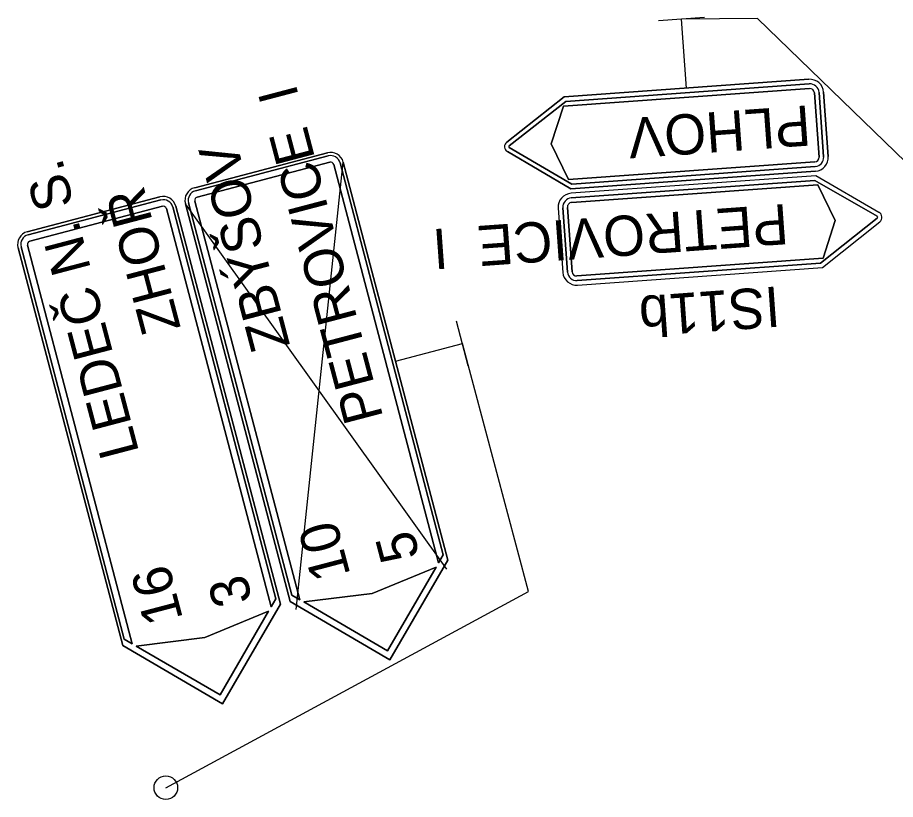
# Model space of a CAD drawing. Extents: x -688893 to -679983, y -1088371 to -1075771.
# Drawn here: x -687166 to -686022, y -1078650 to -1077631 of the extents above; entities that cross this region are included whole.
import ezdxf

# ---------------------------------------------------------------- set-up
doc = ezdxf.new("R2010")
doc.units = 0
for name, color, linetype in [('S SDZ', 7, 'Continuous'), ('S SDZ plochy', 7, 'Continuous'), ('S SDZ symbol', 7, 'Continuous'), ('SDZ', 7, 'Continuous'), ('SDZ ozn', 7, 'Continuous'), ('SDZ plochy', 7, 'Continuous'), ('SDZ symbol', 7, 'Continuous')]:
    doc.layers.add(name, color=color, linetype=linetype)

msp = doc.modelspace()

# ---------------------------------------------------------------- linework, layer by layer
at = {"layer": 'S SDZ'}
for p, q in [((-686762.4, -1077806.8), (-686935.3, -1077852.3)), ((-686761.3, -1077810.9), (-686934.2, -1077856.4)), ((-686932, -1077864.6), (-686759.2, -1077819.2)), ((-686617.5, -1078341.1), (-686754, -1077822.2)), ((-686611.4, -1078330.7), (-686745.8, -1077820)), ((-686605.2, -1078337.5), (-686741.6, -1077818.9)), ((-686980.6, -1077864.2), (-687153.4, -1077909.7)), ((-686979.5, -1077868.3), (-687152.3, -1077913.8)), ((-686943.3, -1077872), (-686808.8, -1078383.1)), ((-686935.1, -1077869.8), (-686798.4, -1078389.2)), ((-687150.2, -1077922), (-686977.3, -1077876.5)), ((-686835.6, -1078398.5), (-686972.1, -1077879.6)), ((-686829.5, -1078388.1), (-686963.9, -1077877.4)), ((-686823.3, -1078394.9), (-686959.8, -1077876.3)), ((-686947.4, -1077873.1), (-686811, -1078391.6)), ((-687161.4, -1077929.4), (-687027, -1078440.5)), ((-687153.2, -1077927.2), (-687016.6, -1078446.6)), ((-687165.5, -1077930.5), (-687029.1, -1078449)), ((-686681, -1078467.5), (-686605.2, -1078337.5)), ((-686617.5, -1078341.1), (-686611.4, -1078330.7)), ((-686620.8, -1078346.9), (-686703.8, -1078381)), ((-686684.1, -1078455.9), (-686620.8, -1078346.9)), ((-686808.8, -1078383.1), (-686798.4, -1078389.2)), ((-686703.8, -1078381), (-686793.2, -1078392.2)), ((-686899.2, -1078524.8), (-686823.3, -1078394.9)), ((-686835.6, -1078398.5), (-686829.5, -1078388.1)), ((-686811, -1078391.6), (-686681, -1078467.5)), ((-686793.2, -1078392.2), (-686684.1, -1078455.9)), ((-686838.9, -1078404.3), (-686921.9, -1078438.4)), ((-686902.2, -1078513.3), (-686838.9, -1078404.3)), ((-687027, -1078440.5), (-687016.6, -1078446.6)), ((-686921.9, -1078438.4), (-687011.4, -1078449.6)), ((-687029.1, -1078449), (-686899.2, -1078524.8)), ((-687011.4, -1078449.6), (-686902.2, -1078513.3))]:
    msp.add_line(p, q, dxfattribs=at)
for centre, radius, start, end in [((-686758.1, -1077823.3), 17, 14.7382, 104.7382), ((-686758.1, -1077823.3), 12.8, 14.7382, 104.7382), ((-686758.1, -1077823.3), 4.26, 14.7382, 104.7382), ((-686931, -1077868.7), 17, 104.7382, 194.7382), ((-686931, -1077868.7), 12.8, 104.7382, 194.7382), ((-686976.2, -1077880.7), 17, 14.7382, 104.7382), ((-686976.2, -1077880.7), 12.8, 14.7382, 104.7382), ((-686931, -1077868.7), 4.26, 104.7382, 194.7382), ((-686976.2, -1077880.7), 4.26, 14.7382, 104.7382), ((-687149.1, -1077926.1), 17, 104.7382, 194.7382), ((-687149.1, -1077926.1), 12.8, 104.7382, 194.7382), ((-687149.1, -1077926.1), 4.26, 104.7382, 194.7382)]:
    msp.add_arc(centre, radius, start, end, dxfattribs=at)
at = {"layer": 'S SDZ plochy'}
for p, q in [((-686935.3, -1077852.3), (-686762.4, -1077806.8)), ((-686761.3, -1077810.9), (-686934.2, -1077856.4)), ((-686934.2, -1077856.4), (-686761.3, -1077810.9)), ((-686932, -1077864.6), (-686759.2, -1077819.2)), ((-686759.2, -1077819.2), (-686932, -1077864.6)), ((-686754, -1077822.2), (-686617.5, -1078341.1)), ((-686617.5, -1078341.1), (-686754, -1077822.2)), ((-686611.4, -1078330.7), (-686745.8, -1077820)), ((-686745.8, -1077820), (-686611.4, -1078330.7)), ((-686741.6, -1077818.9), (-686605.2, -1078337.5)), ((-687153.4, -1077909.7), (-686980.6, -1077864.2)), ((-686979.5, -1077868.3), (-687152.3, -1077913.8)), ((-687152.3, -1077913.8), (-686979.5, -1077868.3)), ((-686943.3, -1077872), (-686808.8, -1078383.1)), ((-686808.8, -1078383.1), (-686943.3, -1077872)), ((-686798.4, -1078389.2), (-686935.1, -1077869.8)), ((-686935.1, -1077869.8), (-686798.4, -1078389.2)), ((-687150.2, -1077922), (-686977.3, -1077876.5)), ((-686977.3, -1077876.5), (-687150.2, -1077922)), ((-686972.1, -1077879.6), (-686835.6, -1078398.5)), ((-686835.6, -1078398.5), (-686972.1, -1077879.6)), ((-686829.5, -1078388.1), (-686963.9, -1077877.4)), ((-686963.9, -1077877.4), (-686829.5, -1078388.1)), ((-686959.8, -1077876.3), (-686823.3, -1078394.9)), ((-686811, -1078391.6), (-686947.4, -1077873.1)), ((-687161.4, -1077929.4), (-687027, -1078440.5)), ((-687027, -1078440.5), (-687161.4, -1077929.4)), ((-687016.6, -1078446.6), (-687153.2, -1077927.2)), ((-687153.2, -1077927.2), (-687016.6, -1078446.6)), ((-687029.1, -1078449), (-687165.5, -1077930.5)), ((-686605.2, -1078337.5), (-686681, -1078467.5)), ((-686617.5, -1078341.1), (-686611.4, -1078330.7)), ((-686611.4, -1078330.7), (-686617.5, -1078341.1)), ((-686703.8, -1078381), (-686620.8, -1078346.9)), ((-686620.8, -1078346.9), (-686703.8, -1078381)), ((-686620.8, -1078346.9), (-686684.1, -1078455.9)), ((-686684.1, -1078455.9), (-686620.8, -1078346.9)), ((-686808.8, -1078383.1), (-686798.4, -1078389.2)), ((-686798.4, -1078389.2), (-686808.8, -1078383.1)), ((-686793.2, -1078392.2), (-686703.8, -1078381)), ((-686703.8, -1078381), (-686793.2, -1078392.2)), ((-686823.3, -1078394.9), (-686899.2, -1078524.8)), ((-686835.6, -1078398.5), (-686829.5, -1078388.1)), ((-686829.5, -1078388.1), (-686835.6, -1078398.5)), ((-686681, -1078467.5), (-686811, -1078391.6)), ((-686684.1, -1078455.9), (-686793.2, -1078392.2)), ((-686793.2, -1078392.2), (-686684.1, -1078455.9)), ((-686921.9, -1078438.4), (-686838.9, -1078404.3)), ((-686838.9, -1078404.3), (-686921.9, -1078438.4)), ((-686838.9, -1078404.3), (-686902.2, -1078513.3)), ((-686902.2, -1078513.3), (-686838.9, -1078404.3)), ((-687027, -1078440.5), (-687016.6, -1078446.6)), ((-687016.6, -1078446.6), (-687027, -1078440.5)), ((-687011.4, -1078449.6), (-686921.9, -1078438.4)), ((-686921.9, -1078438.4), (-687011.4, -1078449.6)), ((-686899.2, -1078524.8), (-687029.1, -1078449)), ((-686902.2, -1078513.3), (-687011.4, -1078449.6)), ((-687011.4, -1078449.6), (-686902.2, -1078513.3))]:
    msp.add_line(p, q, dxfattribs=at)
for centre, radius, start, end in [((-686758.1, -1077823.3), 17, 14.7382, 104.7382), ((-686758.1, -1077823.3), 12.8, 14.7382, 104.7382), ((-686758.1, -1077823.3), 12.8, 14.7382, 104.7382), ((-686758.1, -1077823.3), 4.26, 14.7382, 104.7382), ((-686758.1, -1077823.3), 4.26, 14.7382, 104.7382), ((-686931, -1077868.7), 17, 104.7382, 194.7382), ((-686931, -1077868.7), 12.8, 104.7382, 194.7382), ((-686931, -1077868.7), 12.8, 104.7382, 194.7382), ((-686976.2, -1077880.7), 17, 14.7382, 104.7382), ((-686976.2, -1077880.7), 12.8, 14.7382, 104.7382), ((-686976.2, -1077880.7), 12.8, 14.7382, 104.7382), ((-686931, -1077868.7), 4.26, 104.7382, 194.7382), ((-686931, -1077868.7), 4.26, 104.7382, 194.7382), ((-686976.2, -1077880.7), 4.26, 14.7382, 104.7382), ((-686976.2, -1077880.7), 4.26, 14.7382, 104.7382), ((-687149.1, -1077926.1), 17, 104.7382, 194.7382), ((-687149.1, -1077926.1), 12.8, 104.7382, 194.7382), ((-687149.1, -1077926.1), 12.8, 104.7382, 194.7382), ((-687149.1, -1077926.1), 4.26, 104.7382, 194.7382), ((-687149.1, -1077926.1), 4.26, 104.7382, 194.7382)]:
    msp.add_arc(centre, radius, start, end, dxfattribs=at)
at = {"layer": 'SDZ'}
for p, q in [((-686271, -1077630.6), (-686330.8, -1077634.8)), ((-686294.4, -1077722.5), (-686300.9, -1077632.7)), ((-686453.9, -1077733.9), (-686134.9, -1077711)), ((-686454.9, -1077746), (-686134.1, -1077723)), ((-686134.5, -1077717), (-686451.7, -1077739.8)), ((-686528.6, -1077792.9), (-686453.9, -1077733.9)), ((-686127.7, -1077728.5), (-686121.7, -1077812.3)), ((-686115.7, -1077811.9), (-686121.7, -1077728.1)), ((-686115.7, -1077727.7), (-686109.7, -1077811.5)), ((-686451.7, -1077739.8), (-686525.5, -1077797.7)), ((-686470.6, -1077795.3), (-686454.9, -1077746)), ((-686525.4, -1077800.1), (-686444, -1077847.5)), ((-686448, -1077841.8), (-686470.6, -1077795.3)), ((-686445.3, -1077853.6), (-686527.8, -1077805.3)), ((-686527.6, -1077805.4), (-686527.6, -1077805.4)), ((-686803.1, -1078402), (-686741.6, -1077818.9)), ((-686127.2, -1077818.7), (-686448, -1077841.8)), ((-686444, -1077847.5), (-686126.8, -1077824.7)), ((-686126.4, -1077830.7), (-686445.3, -1077853.6)), ((-686125.9, -1077836.7), (-686444.9, -1077859.6)), ((-686043.6, -1077884.4), (-686125.9, -1077836.7)), ((-686444.5, -1077865.6), (-686127.3, -1077842.8)), ((-686123.3, -1077848.5), (-686444, -1077871.6)), ((-686127.3, -1077842.8), (-686046, -1077889.6)), ((-686100.7, -1077895), (-686123.3, -1077848.5)), ((-686606.5, -1078349.5), (-686947.4, -1077873.1)), ((-686461.6, -1077878.8), (-686455.6, -1077962.6)), ((-686449.6, -1077962.2), (-686455.6, -1077878.4)), ((-686449.6, -1077878), (-686443.6, -1077961.8)), ((-686045.8, -1077892), (-686119.6, -1077950.5)), ((-686116.4, -1077944.3), (-686100.7, -1077895)), ((-686117.3, -1077956.4), (-686042.6, -1077896.8)), ((-686042.8, -1077896.9), (-686042.8, -1077896.9)), ((-686437.2, -1077967.3), (-686116.4, -1077944.3)), ((-686119.6, -1077950.5), (-686436.7, -1077973.3)), ((-686436.3, -1077979.3), (-686117.3, -1077956.4)), ((-686578.8, -1078084.3), (-686594, -1078026.3)), ((-686673.4, -1078078.2), (-686586.4, -1078055.3))]:
    msp.add_line(p, q, dxfattribs=at)
for points in [[(-685981.4, -1077845.3), (-686202, -1077631.6), (-686300.9, -1077632.7)], [(-686972.9, -1078634.2), (-686500.4, -1078378.4), (-686586.4, -1078055.3)]]:
    msp.add_lwpolyline(points, dxfattribs=at)
msp.add_circle((-686972.9, -1078634.2), 15.4, dxfattribs=at)
for centre, radius, start, end in [((-686133.7, -1077729), 18, 4.1047, 94.1047), ((-686133.7, -1077729), 12, 4.1047, 94.1047), ((-686133.7, -1077729), 6, 4.1047, 94.1047), ((-686524, -1077798.8), 7.5, 128.2965, 239.6147), ((-686524.6, -1077798.8), 1.5, 128.1011, 239.804), ((-686127.6, -1077812.8), 6, 274.1047, 4.1047), ((-686127.6, -1077812.8), 12, 274.1047, 4.1047), ((-686127.6, -1077812.8), 18, 274.1047, 4.1047), ((-686443.6, -1077877.5), 18, 94.1047, 184.1047), ((-686443.6, -1077877.5), 12, 94.1047, 184.1047), ((-686443.6, -1077877.5), 6, 94.1047, 184.1047), ((-686046.7, -1077890.9), 1.5, 308.4053, 60.1082), ((-686047.3, -1077890.9), 7.5, 308.5946, 59.9129), ((-686437.6, -1077961.3), 18, 184.1047, 274.1047), ((-686437.6, -1077961.3), 12, 184.1047, 274.1047), ((-686437.6, -1077961.3), 6, 184.1047, 274.1047)]:
    msp.add_arc(centre, radius, start, end, dxfattribs=at)
at = {"layer": 'SDZ plochy'}
for p, q in [((-686134.9, -1077711), (-686453.9, -1077733.9)), ((-686134.1, -1077723), (-686454.9, -1077746)), ((-686454.9, -1077746), (-686134.1, -1077723)), ((-686451.7, -1077739.8), (-686134.5, -1077717)), ((-686134.5, -1077717), (-686451.7, -1077739.8)), ((-686453.9, -1077733.9), (-686528.6, -1077792.9)), ((-686121.7, -1077812.3), (-686127.7, -1077728.5)), ((-686127.7, -1077728.5), (-686121.7, -1077812.3)), ((-686121.7, -1077728.1), (-686115.7, -1077811.9)), ((-686115.7, -1077811.9), (-686121.7, -1077728.1)), ((-686109.7, -1077811.5), (-686115.7, -1077727.7)), ((-686525.5, -1077797.7), (-686451.7, -1077739.8)), ((-686451.7, -1077739.8), (-686525.5, -1077797.7)), ((-686454.9, -1077746), (-686470.6, -1077795.3)), ((-686470.6, -1077795.3), (-686454.9, -1077746)), ((-686444, -1077847.5), (-686525.4, -1077800.1)), ((-686525.4, -1077800.1), (-686444, -1077847.5)), ((-686470.6, -1077795.3), (-686448, -1077841.8)), ((-686448, -1077841.8), (-686470.6, -1077795.3)), ((-686527.8, -1077805.3), (-686445.3, -1077853.6)), ((-686448, -1077841.8), (-686127.2, -1077818.7)), ((-686127.2, -1077818.7), (-686448, -1077841.8)), ((-686126.8, -1077824.7), (-686444, -1077847.5)), ((-686444, -1077847.5), (-686126.8, -1077824.7)), ((-686445.3, -1077853.6), (-686126.4, -1077830.7)), ((-686125.9, -1077836.7), (-686444.9, -1077859.6)), ((-686043.6, -1077884.4), (-686125.9, -1077836.7)), ((-686444.5, -1077865.6), (-686127.3, -1077842.8)), ((-686127.3, -1077842.8), (-686444.5, -1077865.6)), ((-686123.3, -1077848.5), (-686444, -1077871.6)), ((-686444, -1077871.6), (-686123.3, -1077848.5)), ((-686127.3, -1077842.8), (-686046, -1077889.6)), ((-686046, -1077889.6), (-686127.3, -1077842.8)), ((-686100.7, -1077895), (-686123.3, -1077848.5)), ((-686123.3, -1077848.5), (-686100.7, -1077895)), ((-686461.6, -1077878.8), (-686455.6, -1077962.6)), ((-686449.6, -1077962.2), (-686455.6, -1077878.4)), ((-686455.6, -1077878.4), (-686449.6, -1077962.2)), ((-686449.6, -1077878), (-686443.6, -1077961.8)), ((-686443.6, -1077961.8), (-686449.6, -1077878)), ((-686045.8, -1077892), (-686119.6, -1077950.5)), ((-686119.6, -1077950.5), (-686045.8, -1077892)), ((-686116.4, -1077944.3), (-686100.7, -1077895)), ((-686100.7, -1077895), (-686116.4, -1077944.3)), ((-686117.3, -1077956.4), (-686042.6, -1077896.8)), ((-686437.2, -1077967.3), (-686116.4, -1077944.3)), ((-686116.4, -1077944.3), (-686437.2, -1077967.3)), ((-686119.6, -1077950.5), (-686436.7, -1077973.3)), ((-686436.7, -1077973.3), (-686119.6, -1077950.5)), ((-686436.3, -1077979.3), (-686117.3, -1077956.4))]:
    msp.add_line(p, q, dxfattribs=at)
for centre, radius, start, end in [((-686133.7, -1077729), 18, 4.1047, 94.1047), ((-686133.7, -1077729), 12, 4.1047, 94.1047), ((-686133.7, -1077729), 12, 4.1047, 94.1047), ((-686133.7, -1077729), 6, 4.1047, 94.1047), ((-686133.7, -1077729), 6, 4.1047, 94.1047), ((-686524, -1077798.8), 7.5, 128.2965, 239.6147), ((-686524.6, -1077798.8), 1.5, 128.1011, 239.804), ((-686524.6, -1077798.8), 1.5, 128.1011, 239.804), ((-686127.6, -1077812.8), 6, 274.1047, 4.1047), ((-686127.6, -1077812.8), 6, 274.1047, 4.1047), ((-686127.6, -1077812.8), 12, 274.1047, 4.1047), ((-686127.6, -1077812.8), 12, 274.1047, 4.1047), ((-686127.6, -1077812.8), 18, 274.1047, 4.1047), ((-686443.6, -1077877.5), 18, 94.1047, 184.1047), ((-686443.6, -1077877.5), 12, 94.1047, 184.1047), ((-686443.6, -1077877.5), 12, 94.1047, 184.1047), ((-686443.6, -1077877.5), 6, 94.1047, 184.1047), ((-686443.6, -1077877.5), 6, 94.1047, 184.1047), ((-686046.7, -1077890.9), 1.5, 308.4053, 60.1082), ((-686046.7, -1077890.9), 1.5, 308.4053, 60.1082), ((-686047.3, -1077890.9), 7.5, 308.5946, 59.9129), ((-686437.6, -1077961.3), 18, 184.1047, 274.1047), ((-686437.6, -1077961.3), 12, 184.1047, 274.1047), ((-686437.6, -1077961.3), 12, 184.1047, 274.1047), ((-686437.6, -1077961.3), 6, 184.1047, 274.1047), ((-686437.6, -1077961.3), 6, 184.1047, 274.1047)]:
    msp.add_arc(centre, radius, start, end, dxfattribs=at)

# ---------------------------------------------------------------- texts
at = {"layer": 'S SDZ symbol'}
for s, height, p in [('PETROVICE  I', 51.067, (-686689.3, -1078151.7)), ('ZBÝŠOV', 51.07, (-686810.8, -1078057.9)), ('LEDEČ N. S.', 51.067, (-687007.4, -1078197.1)), ('ZHOŘ', 51.07, (-686953.2, -1078035.2)), ('10', 51.07, (-686732.1, -1078356.9)), ('5', 51.1, (-686641.7, -1078332.7)), ('16', 51.07, (-686950.3, -1078414.2)), ('3', 51.1, (-686859.7, -1078390.3))]:
    msp.add_text(s, height=height, rotation=104.7382, dxfattribs=at).set_placement(p)
at = {"layer": 'SDZ ozn'}
msp.add_text('IS11b', height=52.5, rotation=184.1047, dxfattribs=at).set_placement((-686174.7, -1077980.8))
at = {"layer": 'SDZ symbol'}
for s, p in [('PLHOV', (-686134.7, -1077744.8)), ('PETROVICE  I', (-686163.8, -1077873.3))]:
    msp.add_text(s, height=52.5, rotation=184.1047, dxfattribs=at).set_placement(p)

doc.saveas('drawing.dxf')
